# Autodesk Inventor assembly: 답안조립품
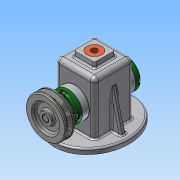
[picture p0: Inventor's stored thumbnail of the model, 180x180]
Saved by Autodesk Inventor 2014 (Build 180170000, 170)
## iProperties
Created: 2017-07
Part Number: 답안조립품
Document SubType Name: Assembly
Designer: NET
Author: NET
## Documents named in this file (16)
- C:\Users\NET\Desktop\470707V1024\답안조립품.iam
- C:\Users\NET\Desktop\470707V1024\본체.ipt
- C:\Users\NET\Desktop\470707V1024\V벨트풀리.ipt
- C:\Users\NET\Desktop\470707V1024\고정핀 1.2 x  8.ipt
- C:\Users\NET\Desktop\470707V1024\뒤커버.ipt
- C:\Users\NET\Desktop\470707V1024\링크.ipt
- C:\Users\NET\Desktop\470707V1024\멈춤나사 M3x8.ipt
- C:\Users\NET\Desktop\470707V1024\베어링 12 x 32 x 10.ipt
- C:\Users\NET\Desktop\470707V1024\볼트 M4 x 12.ipt
- C:\Users\NET\Desktop\470707V1024\부시.ipt
- C:\Users\NET\Desktop\470707V1024\슬라이드.ipt
- C:\Users\NET\Desktop\470707V1024\앞커버.ipt
- C:\Users\NET\Desktop\470707V1024\오일실 12 25 7.ipt
- C:\Users\NET\Desktop\470707V1024\키 4 x 4 x 10.ipt
- C:\Users\NET\Desktop\470707V1024\편심축.ipt
- C:\Users\NET\Desktop\470707V1024\핀 5 x 18.ipt
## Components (3 placed, 3 different names)
1. V벨트풀리:1 — 각도:1
2. 고정핀 1.2 x  8:1 — 플러쉬:1
3. 핀 5 x 18:1
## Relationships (2: Angle 1, Flush 1)
- 각도:1 [Angle]: V벨트풀리:1
- 플러쉬:1 [Flush]: 고정핀 1.2 x  8:1
